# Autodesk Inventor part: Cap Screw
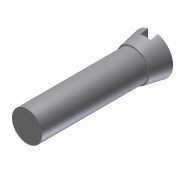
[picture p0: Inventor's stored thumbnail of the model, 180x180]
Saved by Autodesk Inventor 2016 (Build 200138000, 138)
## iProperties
Shininess: 77.0
Length Units: 11269
Angle Units: 11279
Time Units: 11290
Mass Units: 11283
Length Display Precision: 3
Angle Display Precision: 2
Created: 2002-02
Part Number: Cap Screw
Document SubType Name: Modeling
Designer: ***
Density: 1 g/cm^3
Material: Generic
Mass: 0.736586 g
Surface Area: 5.87035 cm^2
Volume: 0.736586 cm^3
Appearance: Default
Density: 0.0
Volumn: 0.0
Area: 0.0
PropertySet Name: Model Information
Control State: 0
Master: False
Checked Out: False
Author: ***
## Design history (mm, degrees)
sketch "Sketch1"
  geometry: L1 (0, 27.83)-(4, 27.83); L2 (4, 27.83)-(3.25, 23.83); L3 (3.25, 23.83)-(0, 23.83); L4 (0, 23.83)-(0, 27.83)
  constraints: 8 end point, 1 horizontal, 1 parallel, 1 perpendicular, 1 point on line
  dimensions: "d2" = 4 distance from line of L1 L2.end; "d5" = 8 diameter of L1.end L4; "d6" = 6.5 diameter of L3.start L4; "d14" = 4 distance of L3.end L1.start
revolve "Revolution1" sketch "Sketch1" stored, may be unused: angle "d7" = 90 deg
sketch "Sketch2"
  geometry: C1 r 3 at (0, 0)
  constraints: 1 centre point
  dimensions: "d8" = 6 diameter of C1
extrude "Extrusion1" join sketch "Sketch2" distance "d9" = 21; taper "d10" = 0 deg
sketch "Sketch3"
  geometry: L1 (-1, 28.967)-(1, 28.967); L2 (1, 28.967)-(1, 26.33); L3 (1, 26.33)-(-1, 26.33); L4 (-1, 26.33)-(-1, 28.967); L5 (-4, 27.83)-(4, 27.83) reference
  constraints: 8 end point, 2 parallel, 1 horizontal, 1 perpendicular
  dimensions: "d11" = 2 distance of L1.start L1.end; "d15" = 1.5 distance between parallel lines of L5 L3
extrude "Extrusion2" cut sketch "Sketch3" stored distance "d12" = 24; taper "d13" = 0 deg
body "Solid1"
